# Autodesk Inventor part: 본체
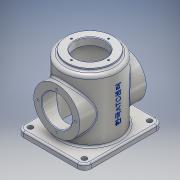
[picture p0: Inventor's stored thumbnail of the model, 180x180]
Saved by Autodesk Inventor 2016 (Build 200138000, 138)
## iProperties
Created: 2021-02
Part Number: 본체
Material: 알루미늄 6061
Document SubType Name: Modeling
Designer: user
Density: 2.7 g/cm^3
Appearance: 알루미늄 - 평지
Mass: 1235.48 g
Surface Area: 1067.6 cm^2
Volume: 457.584 cm^3
Author: user
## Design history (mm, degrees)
sketch "스케치1"
  geometry: L1 (60, -70)-(-60, -70); L2 (-60, -70)-(-60, 70); L3 (-60, 70)-(60, 70); L4 (60, 70)-(60, -70); L5 (60, -70)-(-60, 70); L6 (-60, -70)-(60, 70); 1 further point
  constraints: 12 end point, 2 midpoint, 2 parallel, 1 horizontal, 1 perpendicular
  dimensions: "d0" = 120 distance of L2.end L3.end; "d1" = 140 distance of L1.end L2.end
extrude "돌출1" new body sketch "스케치1" distance "d3" = 10; taper "d4" = 0 deg
sketch "스케치2"
  geometry: C1 r 50 at (0, 0); 1 further point
  constraints: 1 centre point, 1 coincident
  dimensions: "d5" = 100 diameter of C1
extrude "돌출2" join sketch "스케치2" distance "d6" = 110; taper "d7" = 0 deg
sketch "스케치3"
  geometry: C1 r 41 at (0, 0); 1 further point
  constraints: 1 centre point, 1 coincident
  dimensions: "d8" = 82 diameter of C1
extrude "돌출3" join sketch "스케치3" distance "d9" = 5; taper "d10" = 0 deg
node "작업 평면1"
sketch "스케치4"
  geometry: L1 (-60, 0)-(60, 0) reference; C1 r 41 at (0, 60); 2 further points
  constraints: 1 centre point, 1 midpoint, 1 vertical alignment
  dimensions: "d12" = 82 diameter of C1; "d13" = 60 distance from line of C1.centre L1
extrude "돌출4" join sketch "스케치4" stored distance "d14" = 5; taper "d15" = 0 deg
hole "구멍1" diameter "d18" = 54; stored, may be unused: countersink angle "d22" = 90 deg, drill point angle "d24" = 118 deg; dims "d16" = 10, "d17" = 10, "d19" = 6, "d20" = 4, "d21" = 2, "d23" = 8
sketch "스케치5"
  geometry: C1 r 42 at (0, 0); 1 further point
  constraints: 1 centre point, 1 coincident
  dimensions: "d25" = 84 diameter of C1
extrude "돌출5" cut sketch "스케치5" distance "d26" = 112; taper "d27" = 0 deg
hole "구멍2" diameter "d30" = 54; stored, may be unused: countersink angle "d34" = 90 deg, drill point angle "d36" = 0 deg; dims "d28" = 10, "d29" = 10, "d31" = 6, "d32" = 4, "d33" = 2, "d35" = 13
fillet "모깎기1" dims "d37" = 12
hole "구멍3" diameter "d40" = 9; stored, may be unused: countersink angle "d44" = 90 deg, drill point angle "d46" = 0 deg; dims "d38" = 10, "d39" = 10, "d41" = 6, "d42" = 4, "d43" = 2, "d45" = 13
sketch "스케치6"
  geometry: L1 (0, 0)-(0, 33)
  constraints: 2 end point, 1 vertical
  dimensions: "d53" = 33 distance of L1.start L1.end
hole "구멍4" sketch "스케치6" at (0, 33) diameter "d54" = 3.242; stored, may be unused: countersink angle "d58" = 90 deg, drill point angle "d60" = 118 deg; dims "d55" = 8, "d56" = 4, "d57" = 2, "d59" = 10
sketch "스케치7"
  geometry: L1 (0, 0)-(0, 33); C1 r 41 at (0, 0) reference; 1 further point
  constraints: 2 end point, 1 vertical
  dimensions: "d64" = 33 distance of L1.start L1.end
hole "구멍5" sketch "스케치7" at (0, 33) diameter "d65" = 3.242; stored, may be unused: countersink angle "d69" = 90 deg, drill point angle "d71" = 118 deg; dims "d66" = 8, "d67" = 4, "d68" = 2, "d70" = 10
chamfer "모따기1" distance "d75" = 1; stored, may be unused: second distance "d76" = 2, angle "d77" = 45 deg
fillet "모깎기2" dims "d78" = 6
fillet "모깎기3" dims "d79" = 3
fillet "모깎기4" dims "d80" = 3
node "작업 평면2"
sketch "스케치8"
  geometry: L1 (58, 0)-(-58, 0) reference; 3 further points
  constraints: 1 midpoint, 1 vertical alignment, 1 other
  dimensions: "d82" = 66 distance from line of L1 point (0, 66)
feature "엠보싱1" sketch "스케치8" dims "d0" = 120, "d1" = 140, "d83" = 0.5, "d84" = 0
node "솔리드1"
mirror "대칭1"
pattern_linear "직사각형 패턴1" dims "d49" = 116, "d52" = 96
pattern_circular "원형 패턴1" dims angle "d62" = 360 deg
pattern_circular "원형 패턴2" dims angle "d73" = 360 deg
mirror "대칭2"
other parameters: "d11" = -59, "d81" = 53.25
